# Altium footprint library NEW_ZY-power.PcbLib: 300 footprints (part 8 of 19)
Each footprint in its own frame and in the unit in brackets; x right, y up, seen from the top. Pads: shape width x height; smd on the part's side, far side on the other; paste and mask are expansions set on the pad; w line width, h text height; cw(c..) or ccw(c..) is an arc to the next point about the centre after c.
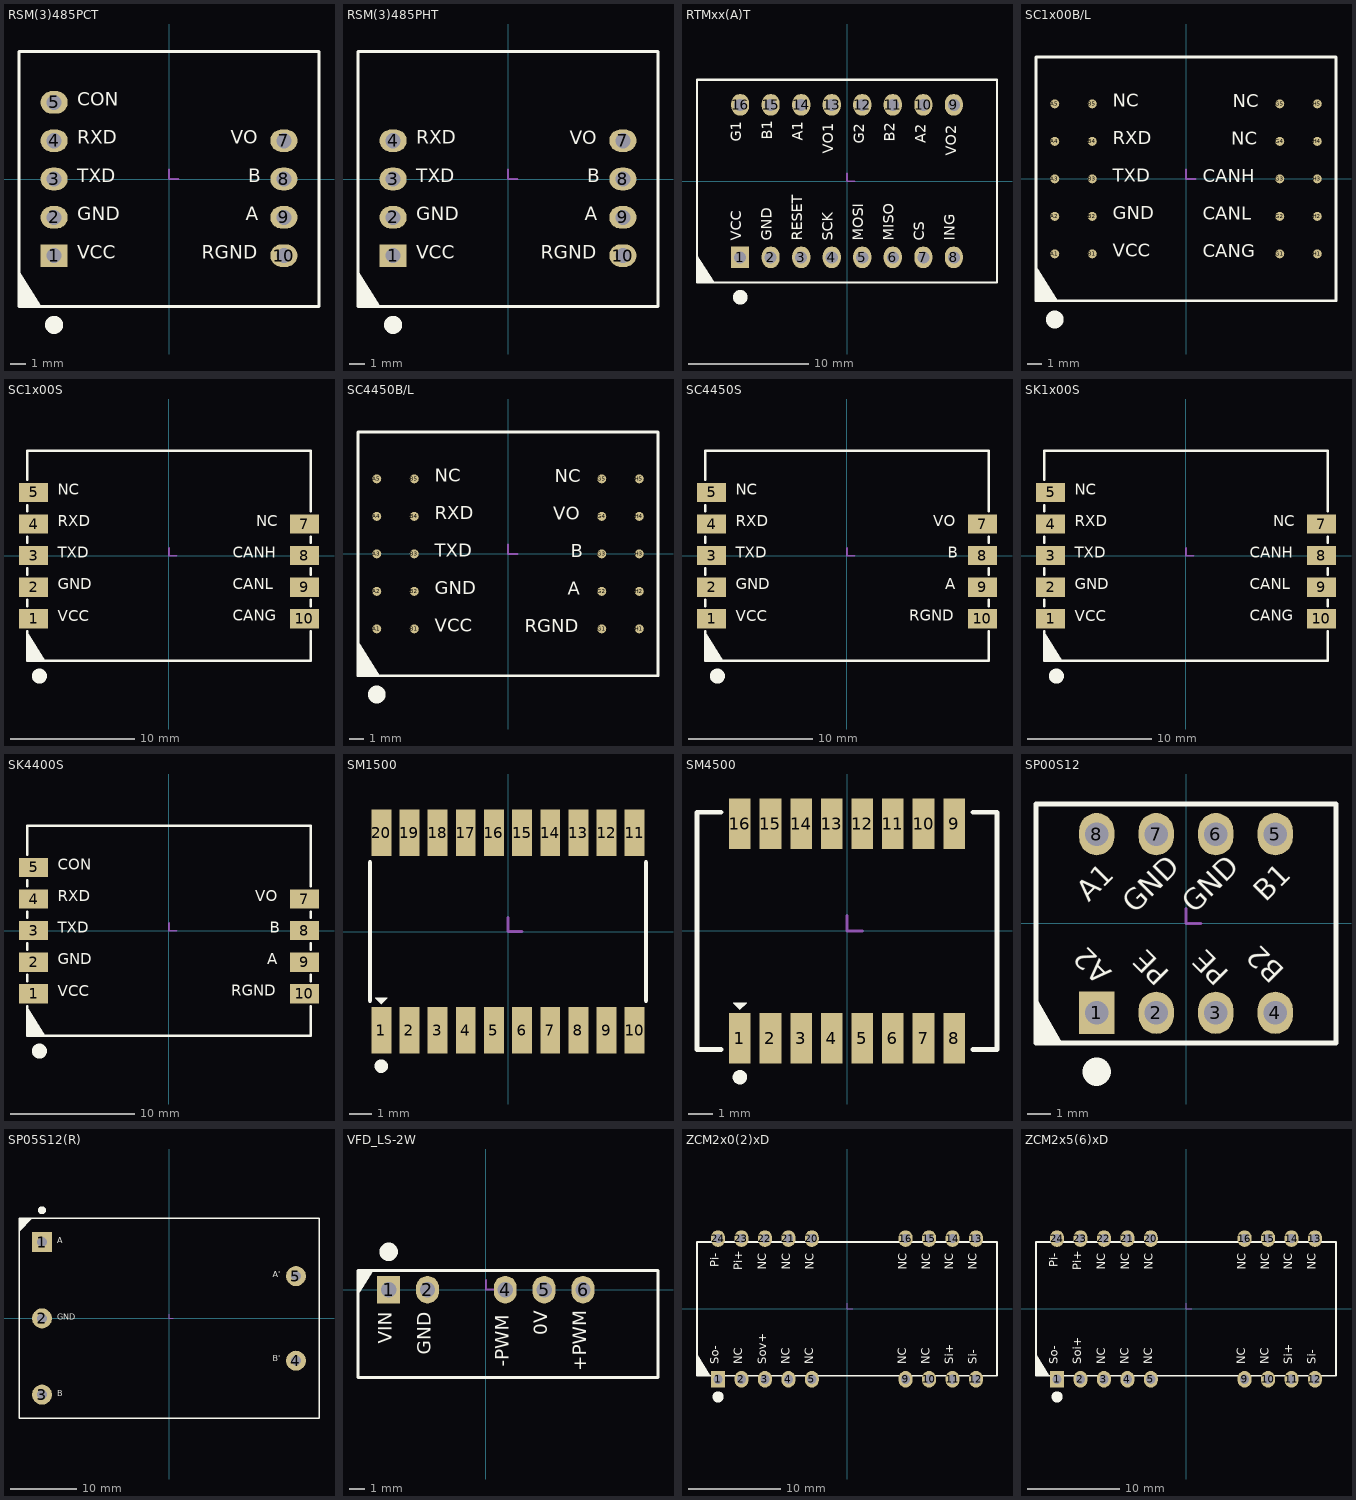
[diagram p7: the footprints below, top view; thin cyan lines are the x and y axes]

## RSM(3)485PCT [mm]
height 7.05
pads (9):
  rect 1.8x1.5 hole 1: 1(-7.62,-5.08)
  oval 1.8x1.5 hole 1: 2(-7.62,-2.54) 3(-7.62,0) 4(-7.62,2.54) 5(-7.62,5.08) 7(7.62,2.54) 8(7.62,0) 9(7.62,-2.54) 10(7.62,-5.08)
Top Overlay:
  circle w1: c-7.62,-9.675 r0.1
  region: -9.95,-6.12 -9.95,-8.45 -8.49,-8.45
  lines w0.2: -9.95,-8.45 -9.95,8.45 9.95,8.45 9.95,-8.45 -9.95,-8.45
  text "VO" at 4.088,2.032 h1.52
  text "VCC" at -6.096,-5.588 h1.52
  text "CON" at -6.097,4.572 h1.52
  text "GND" at -6.097,-3.048 h1.52
  text "RXD" at -6.097,2.032 h1.52
  text "TXD" at -6.097,-0.508 h1.52
  text "RGND" at 2.159,-5.588 h1.52
  text "B" at 5.253,-0.508 h1.52
  text "A" at 5.079,-3.048 h1.52
Mechanical 15:
  lines w0.127: 0,0.635 0,0 0.635,0

## RSM(3)485PHT [mm]
height 7.05
pads (8):
  rect 1.8x1.5 hole 1: 1(-7.62,-5.08)
  oval 1.8x1.5 hole 1: 2(-7.62,-2.54) 3(-7.62,0) 4(-7.62,2.54) 7(7.62,2.54) 8(7.62,0) 9(7.62,-2.54) 10(7.62,-5.08)
Top Overlay:
  circle w1: c-7.62,-9.675 r0.1
  region: -9.95,-6.12 -9.95,-8.45 -8.49,-8.45
  lines w0.2: -9.95,-8.45 9.95,-8.45 9.95,8.45 -9.95,8.45 -9.95,-8.45
  text "VO" at 4.088,2.007 h1.52
  text "A" at 5.079,-3.048 h1.52
  text "B" at 5.253,-0.508 h1.52
  text "RGND" at 2.159,-5.588 h1.52
  text "TXD" at -6.097,-0.508 h1.52
  text "RXD" at -6.097,2.032 h1.52
  text "GND" at -6.097,-3.048 h1.52
  text "VCC" at -6.096,-5.588 h1.52
Mechanical 15:
  lines w0.127: 0,0.635 0,0 0.635,0

## RTMxx(A)T [mm]
height 7.1
pads (16):
  rect 1.5x1.8 hole 1: 1(-8.89,-6.35)
  oval 1.5x1.8 hole 1: 2(-6.35,-6.35) 3(-3.81,-6.35) 4(-1.27,-6.35) 5(1.27,-6.35) 6(3.81,-6.35) 7(6.35,-6.35) 8(8.89,-6.35) 9(8.89,6.35) 10(6.35,6.35) 11(3.81,6.35) 12(1.27,6.35) 13(-1.27,6.35) 14(-3.81,6.35) 15(-6.35,6.35) 16(-8.89,6.35)
Top Overlay:
  circle w1: c-8.89,-9.675 r0.1
  region: -12.49,-6.12 -12.49,-8.45 -11.03,-8.45
  lines w0.2: -12.49,-8.45 12.49,-8.45 12.49,8.45 -12.49,8.45 -12.49,-8.45
  text "G1" at -8.509,3.265 h1.52
  text "B1" at -5.951,3.442 h1.52
  text "A1" at -3.393,3.341 h1.52
  text "VO1" at -0.835,2.289 h1.52
  text "G2" at 1.724,3.086 h1.52
  text "B2" at 4.282,3.263 h1.52
  text "MISO" at 4.191,-4.953 h1.52
  text "MOSI" at 1.651,-4.953 h1.52
  text "SCK" at -0.889,-4.953 h1.52
  text "RESET" at -3.429,-4.953 h1.52
  text "GND" at -5.969,-4.953 h1.52
  text "A2" at 6.84,3.162 h1.52
  text "VCC" at -8.509,-4.953 h1.52
  text "CS" at 6.731,-4.953 h1.52
  text "ING" at 9.271,-4.953 h1.52
  text "VO2" at 9.398,2.11 h1.52
Mechanical 15:
  lines w0.127: 0,0.635 0,0 0.635,0

## SC1x00B/L [mm]
height 5.5
pads (20):
  round 0.61 smd: A1(-8.89,-5.08) A2(-8.89,-2.54) A3(-8.89,0) A4(-8.89,2.54) A5(-8.89,5.08) B1(-6.35,-5.08) B2(-6.35,-2.54) B3(-6.35,0) B4(-6.35,2.54) B5(-6.35,5.08) G1(6.35,-5.08) G2(6.35,-2.54) G3(6.35,0) G4(6.35,2.54) G5(6.35,5.08) H1(8.89,-5.08) H2(8.89,-2.54) H3(8.89,0) H4(8.89,2.54) H5(8.89,5.08)
Top Overlay:
  circle w1: c-8.89,-9.525 r0.1
  region: -10.16,-5.925 -10.16,-8.255 -8.7,-8.255
  lines w0.2: -10.16,-8.255 -10.16,8.255 10.16,8.255 10.16,-8.255 -10.16,-8.255
  text "VCC" at -4.953,-5.588 h1.52
  text "GND" at -4.954,-3.048 h1.52
  text "TXD" at -4.954,-0.508 h1.52
  text "RXD" at -4.954,2.032 h1.52
  text "NC" at -4.954,4.572 h1.52
  text "NC" at 3.164,4.556 h1.52
  text "NC" at 3.072,2.016 h1.52
  text "CANH" at 1.143,-0.524 h1.52
  text "CANL" at 1.143,-3.064 h1.52
  text "CANG" at 1.143,-5.604 h1.52
Mechanical 15:
  lines w0.127: 0,0.635 0,0 0.635,0

## SC1x00S [mm]
height 5.5
pads (9):
  rect 2.35x1.55 smd: 1(-10.9,-5.08) 2(-10.9,-2.54) 3(-10.9,0) 4(-10.9,2.54) 5(-10.9,5.08) 7(10.9,2.54) 8(10.9,0) 9(10.9,-2.54) 10(10.9,-5.08)
Top Overlay:
  circle w1: c-10.438,-9.703 r0.1
  region: -11.43,-6.12 -11.43,-8.45 -9.97,-8.45
  lines w0.2: -11.43,-6.096 -11.43,-8.45 11.43,-8.45 11.43,-6.096 ; -11.43,-4.064 -11.43,-3.556 ; -11.43,-1.524 -11.43,-1.016 ; -11.43,1.016 -11.43,1.524 ; -11.43,3.556 -11.43,4.064 ; -11.43,6.096 -11.43,8.45 11.43,8.45 11.43,3.556 ; 11.43,-4.064 11.43,-3.556 ; 11.43,-1.524 11.43,-1.016 ; 11.43,1.016 11.43,1.524
  text "CANG" at 5.132,-5.572 h1.52
  text "CANL" at 5.132,-3.032 h1.52
  text "CANH" at 5.132,-0.492 h1.52
  text "NC" at 7.004,2.048 h1.52
  text "NC" at -8.965,4.572 h1.52
  text "RXD" at -8.965,2.032 h1.52
  text "TXD" at -8.965,-0.508 h1.52
  text "GND" at -8.965,-3.048 h1.52
  text "VCC" at -8.965,-5.588 h1.52
Mechanical 15:
  lines w0.127: 0,0.635 0,0 0.635,0

## SC4450B/L [mm]
height 6
pads (20):
  round 0.61 smd: A1(-8.89,-5.08) A2(-8.89,-2.54) A3(-8.89,0) A4(-8.89,2.54) A5(-8.89,5.08) B1(-6.35,-5.08) B2(-6.35,-2.54) B3(-6.35,0) B4(-6.35,2.54) B5(-6.35,5.08) G1(6.35,-5.08) G2(6.35,-2.54) G3(6.35,0) G4(6.35,2.54) G5(6.35,5.08) H1(8.89,-5.08) H2(8.89,-2.54) H3(8.89,0) H4(8.89,2.54) H5(8.89,5.08)
Top Overlay:
  circle w1: c-8.89,-9.525 r0.1
  region: -10.16,-5.925 -10.16,-8.255 -8.7,-8.255
  lines w0.2: -10.16,-8.255 -10.16,8.255 10.16,8.255 10.16,-8.255 -10.16,-8.255
  text "VCC" at -4.953,-5.588 h1.52
  text "GND" at -4.954,-3.048 h1.52
  text "TXD" at -4.954,-0.508 h1.52
  text "RXD" at -4.954,2.032 h1.52
  text "NC" at -4.954,4.572 h1.52
  text "NC" at 3.164,4.556 h1.52
  text "VO" at 3.072,2.016 h1.52
  text "B" at 4.237,-0.524 h1.52
  text "A" at 4.063,-3.064 h1.52
  text "RGND" at 1.143,-5.604 h1.52
Mechanical 15:
  lines w0.127: 0,0.635 0,0 0.635,0

## SC4450S [mm]
height 5.5
pads (9):
  rect 2.35x1.55 smd: 1(-10.9,-5.08) 2(-10.9,-2.54) 3(-10.9,0) 4(-10.9,2.54) 5(-10.9,5.08) 7(10.9,2.54) 8(10.9,0) 9(10.9,-2.54) 10(10.9,-5.08)
Top Overlay:
  circle w1: c-10.438,-9.703 r0.1
  region: -11.43,-6.12 -11.43,-8.45 -9.97,-8.45
  lines w0.2: -11.43,-6.096 -11.43,-8.45 11.43,-8.45 11.43,-6.096 ; -11.43,-4.064 -11.43,-3.556 ; -11.43,-1.524 -11.43,-1.016 ; -11.43,1.016 -11.43,1.524 ; -11.43,3.556 -11.43,4.064 ; -11.43,6.096 -11.43,8.45 11.43,8.45 11.43,3.556 ; 11.43,-4.064 11.43,-3.556 ; 11.43,-1.524 11.43,-1.016 ; 11.43,1.016 11.43,1.524
  text "VCC" at -8.965,-5.588 h1.52
  text "GND" at -8.965,-3.048 h1.52
  text "TXD" at -8.965,-0.508 h1.52
  text "RXD" at -8.965,2.032 h1.52
  text "NC" at -8.965,4.572 h1.52
  text "VO" at 6.933,2.048 h1.52
  text "B" at 8.098,-0.492 h1.52
  text "A" at 7.925,-3.032 h1.52
  text "RGND" at 5.005,-5.572 h1.52
Mechanical 15:
  lines w0.127: 0,0.635 0,0 0.635,0

## SK1x00S [mm]
height 5.5
pads (9):
  rect 2.35x1.55 smd: 1(-10.9,-5.08) 2(-10.9,-2.54) 3(-10.9,0) 4(-10.9,2.54) 5(-10.9,5.08) 7(10.9,2.54) 8(10.9,0) 9(10.9,-2.54) 10(10.9,-5.08)
Top Overlay:
  circle w1: c-10.438,-9.703 r0.1
  region: -11.43,-6.12 -11.43,-8.45 -9.97,-8.45
  lines w0.2: -11.43,-6.096 -11.43,-8.45 11.43,-8.45 11.43,-6.096 ; -11.43,-4.064 -11.43,-3.556 ; -11.43,-1.524 -11.43,-1.016 ; -11.43,1.016 -11.43,1.524 ; -11.43,3.556 -11.43,4.064 ; -11.43,6.096 -11.43,8.45 11.43,8.45 11.43,3.556 ; 11.43,-4.064 11.43,-3.556 ; 11.43,-1.524 11.43,-1.016 ; 11.43,1.016 11.43,1.524
  text "VCC" at -8.965,-5.588 h1.52
  text "GND" at -8.965,-3.048 h1.52
  text "TXD" at -8.965,-0.508 h1.52
  text "RXD" at -8.965,2.032 h1.52
  text "NC" at -8.965,4.572 h1.52
  text "NC" at 7.004,2.048 h1.52
  text "CANH" at 5.132,-0.492 h1.52
  text "CANL" at 5.132,-3.032 h1.52
  text "CANG" at 5.132,-5.572 h1.52
Mechanical 15:
  lines w0.127: 0,0.635 0,0 0.635,0

## SK4400S [mm]
height 5.5
pads (9):
  rect 2.35x1.55 smd: 1(-10.9,-5.08) 2(-10.9,-2.54) 3(-10.9,0) 4(-10.9,2.54) 5(-10.9,5.08) 7(10.9,2.54) 8(10.9,0) 9(10.9,-2.54) 10(10.9,-5.08)
Top Overlay:
  circle w1: c-10.438,-9.703 r0.1
  region: -11.43,-6.12 -11.43,-8.45 -9.97,-8.45
  lines w0.2: -11.43,-6.096 -11.43,-8.45 11.43,-8.45 11.43,-6.096 ; -11.43,-4.064 -11.43,-3.556 ; -11.43,-1.524 -11.43,-1.016 ; -11.43,1.016 -11.43,1.524 ; -11.43,3.556 -11.43,4.064 ; -11.43,6.096 -11.43,8.45 11.43,8.45 11.43,3.556 ; 11.43,-4.064 11.43,-3.556 ; 11.43,-1.524 11.43,-1.016 ; 11.43,1.016 11.43,1.524
  text "VCC" at -8.965,-5.588 h1.52
  text "GND" at -8.965,-3.048 h1.52
  text "TXD" at -8.965,-0.508 h1.52
  text "RXD" at -8.965,2.032 h1.52
  text "CON" at -8.965,4.572 h1.52
  text "VO" at 6.933,2.048 h1.52
  text "B" at 8.098,-0.492 h1.52
  text "A" at 7.925,-3.032 h1.52
  text "RGND" at 5.005,-5.572 h1.52
Mechanical 15:
  lines w0.127: 0,0.635 0,0 0.635,0

## SM1500 [mm]
height 3
pads (20):
  rect 0.9x2.1 smd: 1(-5.715,-4.45) 2(-4.445,-4.45) 3(-3.175,-4.45) 4(-1.905,-4.45) 5(-0.635,-4.45) 6(0.635,-4.45) 7(1.905,-4.45) 8(3.175,-4.45) 9(4.445,-4.45) 10(5.715,-4.45) 11(5.715,4.45) 12(4.445,4.45) 13(3.175,4.45) 14(1.905,4.45) 15(0.635,4.45) 16(-0.635,4.45) 17(-1.905,4.45) 18(-3.175,4.45) 19(-4.445,4.45) 20(-5.715,4.45)
Top Overlay:
  circle w0.4: c-5.715,-6.074 r0.1
  region: -5.99,-2.986 -5.715,-3.261 -5.44,-2.986
  lines w0.051: -5.99,-2.986 -5.44,-2.986 -5.715,-3.261 -5.99,-2.986
  lines w0.2: -6.225,-3.129 -6.225,3.119 ; 6.225,-3.129 6.225,3.119
Mechanical 15:
  lines w0.127: 0,0.635 0,0 0.635,0

## SM4500 [mm]
height 3
pads (16):
  rect 0.9x2.1 smd: 1(-4.445,-4.45) 2(-3.175,-4.45) 3(-1.905,-4.45) 4(-0.635,-4.45) 5(0.635,-4.45) 6(1.905,-4.45) 7(3.175,-4.45) 8(4.445,-4.45) 9(4.445,4.45) 10(3.175,4.45) 11(1.905,4.45) 12(0.635,4.45) 13(-0.635,4.45) 14(-1.905,4.45) 15(-3.175,4.45) 16(-4.445,4.45)
Top Overlay:
  circle w0.4: c-4.445,-6.074 r0.1
  region: -4.72,-2.986 -4.445,-3.261 -4.17,-2.986
  lines w0.051: -4.72,-2.986 -4.17,-2.986 -4.445,-3.261 -4.72,-2.986
  lines w0.2: -5.232,-4.925 -6.225,-4.925 -6.225,4.925 -5.232,4.925 ; 5.232,-4.925 6.225,-4.925 6.225,4.925 5.232,4.925
Mechanical 15:
  lines w0.127: 0,0.635 0,0 0.635,0

## SP00S12 [mm]
height 7.7
pads (8):
  rect 1.5x1.8 hole 1: 1(-3.81,-3.81)
  oval 1.5x1.8 hole 1: 2(-1.27,-3.81) 3(1.27,-3.81) 4(3.81,-3.81) 5(3.81,3.81) 6(1.27,3.81) 7(-1.27,3.81) 8(-3.81,3.81)
Top Overlay:
  circle w1: c-3.81,-6.325 r0.1
  region: -5.284,-5.1 -6.4,-3.161 -6.4,-5.1
  lines w0.2: -6.4,-5.1 6.4,-5.1 6.4,5.1 -6.4,5.1 -6.4,-5.1
  text "A2" at -2.921,-1.849 h1.52
  text "PE" at -0.432,-1.88 h1.52
  text "PE" at 2.108,-1.88 h1.52
  text "B2" at 4.47,-1.778 h1.52
  text "A1" at -3.937,0.674 h1.52
  text "GND" at -1.981,0.178 h1.52
  text "GND" at 0.559,0.178 h1.52
  text "B1" at 3.607,0.674 h1.52
Mechanical 15:
  lines w0.127: 0,0.635 0,0 0.635,0

## SP05S12(R) [mm]
height 21.2
pads (5):
  rect 3x3 hole 1.5: 1(-19.05,11.43)
  round 3 hole 1.5: 2(-19.05,0) 3(-19.05,-11.43) 4(19.05,-6.35) 5(19.05,6.35)
Top Overlay:
  circle w1: c-19.05,16.225 r0.1
  region: -22.5,15 -22.5,13.025 -20.525,15
  lines w0.2: -22.5,-15 22.5,-15 22.5,15 -22.5,15 -22.5,-15
  text "B'" at 15.551,-6.731 h1.52
  text "A'" at 15.551,5.842 h1.52
  text "GND" at -16.764,-0.495 h1.52
  text "A" at -16.764,10.947 h1.52
  text "B" at -16.764,-11.938 h1.52
Mechanical 15:
  lines w0.127: 0,0.635 0,0 0.635,0

## VFD_LS-2W [mm]
pads (5):
  rect 1.5x1.8 hole 1: 1(-6.35,0)
  oval 1.5x1.8 hole 1: 2(-3.81,0) 4(1.27,0) 5(3.81,0) 6(6.35,0)
Top Overlay:
  circle w1: c-6.35,2.475 r0.1
  region: -8.35,-0.336 -8.35,1.25 -7.356,1.25
  lines w0.2: -8.35,-5.75 11.25,-5.75 11.25,1.25 -8.35,1.25 -8.35,-5.75
  text "VIN" at -5.842,-3.538 h1.52
  text "GND" at -3.302,-4.264 h1.52
  text "-PWM" at 1.778,-5.022 h1.52
  text "0V" at 4.318,-2.982 h1.52
  text "+PWM" at 6.858,-5.334 h1.52
Mechanical 15:
  lines w0.127: 0,0.635 0,0 0.635,0

## ZCM2x0(2)xD [mm]
height 8.5
pads (18):
  rect 1.5x1.8 hole 1: 1(-13.97,-7.62)
  oval 1.5x1.8 hole 1: 2(-11.43,-7.62) 3(-8.89,-7.62) 4(-6.35,-7.62) 5(-3.81,-7.62) 9(6.35,-7.62) 10(8.89,-7.62) 11(11.43,-7.62) 12(13.97,-7.62) 13(13.97,7.62) 14(11.43,7.62) 15(8.89,7.62) 16(6.35,7.62) 20(-3.81,7.62) 21(-6.35,7.62) 22(-8.89,7.62) 23(-11.43,7.62) 24(-13.97,7.62)
Top Overlay:
  circle w1: c-13.97,-9.525 r0.1
  region: -16.25,-4.92 -16.25,-7.25 -14.79,-7.25
  lines w0.2: -16.25,-7.25 -16.25,7.25 16.25,7.25 16.25,-7.25 -16.25,-7.25
  text "Pi-" at -13.564,4.509 h1.52
  text "Pi+" at -11.024,4.2 h1.52
  text "NC" at 11.836,4.216 h1.52
  text "NC" at 14.376,4.216 h1.52
  text "Si-" at 14.376,-6.02 h1.52
  text "NC" at 6.756,-6.02 h1.52
  text "NC" at 9.296,-6.02 h1.52
  text "NC" at -5.867,-6.02 h1.52
  text "NC" at -3.327,-6.02 h1.52
  text "Sov+" at -8.433,-6.02 h1.52
  text "NC" at 9.347,4.216 h1.52
  text "NC" at 6.807,4.216 h1.52
  text "NC" at -8.433,4.216 h1.52
  text "NC" at -3.277,4.216 h1.52
  text "So-" at -13.564,-6.02 h1.52
  text "NC" at -5.842,4.216 h1.52
  text "NC" at -11.024,-6.02 h1.52
  text "Si+" at 11.836,-6.02 h1.52
Mechanical 15:
  lines w0.127: 0,0.635 0,0 0.635,0

## ZCM2x5(6)xD [mm]
height 8.5
pads (18):
  rect 1.5x1.8 hole 1: 1(-13.97,-7.62)
  oval 1.5x1.8 hole 1: 2(-11.43,-7.62) 3(-8.89,-7.62) 4(-6.35,-7.62) 5(-3.81,-7.62) 9(6.35,-7.62) 10(8.89,-7.62) 11(11.43,-7.62) 12(13.97,-7.62) 13(13.97,7.62) 14(11.43,7.62) 15(8.89,7.62) 16(6.35,7.62) 20(-3.81,7.62) 21(-6.35,7.62) 22(-8.89,7.62) 23(-11.43,7.62) 24(-13.97,7.62)
Top Overlay:
  circle w1: c-13.97,-9.525 r0.1
  region: -16.25,-4.92 -16.25,-7.25 -14.79,-7.25
  lines w0.2: -16.25,-7.25 -16.25,7.25 16.25,7.25 16.25,-7.25 -16.25,-7.25
  text "Pi-" at -13.564,4.509 h1.52
  text "Pi+" at -11.024,4.2 h1.52
  text "NC" at 11.836,4.216 h1.52
  text "NC" at 14.376,4.216 h1.52
  text "Si-" at 14.376,-6.02 h1.52
  text "NC" at 6.756,-6.02 h1.52
  text "NC" at 9.296,-6.02 h1.52
  text "NC" at -5.867,-6.02 h1.52
  text "NC" at -3.327,-6.02 h1.52
  text "NC" at -8.433,-6.02 h1.52
  text "NC" at 9.347,4.216 h1.52
  text "NC" at 6.807,4.216 h1.52
  text "NC" at -8.433,4.216 h1.52
  text "NC" at -3.277,4.216 h1.52
  text "So-" at -13.564,-6.02 h1.52
  text "NC" at -5.842,4.216 h1.52
  text "Soi+" at -11.024,-6.02 h1.52
  text "Si+" at 11.836,-6.02 h1.52
Mechanical 15:
  lines w0.127: 0,0.635 0,0 0.635,0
